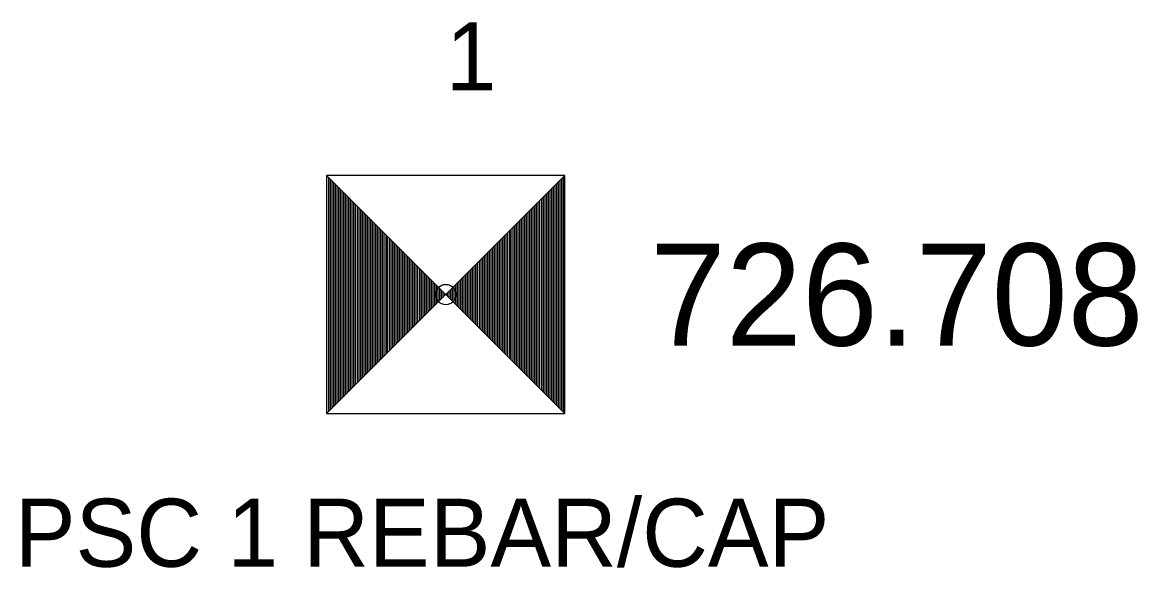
# Model space of a CAD drawing. Extents: x 1655137 to 1657928, y 1003994 to 1005407.
# Drawn here: x 1655137.06 to 1655153.44, y 1005026.6 to 1005034.62 of the extents above; entities that cross this region are included whole.
import ezdxf

# ---------------------------------------------------------------- set-up
doc = ezdxf.new("R2010")
doc.units = 0
for name, color, linetype in [('RD_HC_Survey', 7, 'Continuous'), ('RD_HC_Survey_ELEV', 7, 'Continuous'), ('RD_HC_txCode', 7, 'Continuous'), ('RD_SMD_Locator', 7, 'Continuous')]:
    doc.layers.add(name, color=color, linetype=linetype)

msp = doc.modelspace()

# ---------------------------------------------------------------- linework, layer by layer
at = {"layer": 'RD_HC_Survey'}
for p, q in [((1655141.53, 1005032.367), (1655145.03, 1005028.867)), ((1655145.03, 1005032.367), (1655141.53, 1005028.867)), ((1655141.555, 1005032.343), (1655141.555, 1005028.892)), ((1655141.58, 1005032.318), (1655141.58, 1005028.917)), ((1655141.605, 1005032.293), (1655141.605, 1005028.942)), ((1655141.629, 1005032.268), (1655141.629, 1005028.966)), ((1655141.654, 1005032.244), (1655141.654, 1005028.991)), ((1655141.679, 1005032.219), (1655141.679, 1005029.016)), ((1655141.704, 1005032.194), (1655141.704, 1005029.041)), ((1655144.857, 1005032.194), (1655144.857, 1005029.041)), ((1655144.882, 1005032.219), (1655144.882, 1005029.016)), ((1655144.907, 1005032.244), (1655144.907, 1005028.991)), ((1655144.931, 1005032.268), (1655144.931, 1005028.966)), ((1655144.956, 1005032.293), (1655144.956, 1005028.942)), ((1655144.981, 1005032.318), (1655144.981, 1005028.917)), ((1655145.006, 1005032.343), (1655145.006, 1005028.892)), ((1655141.728, 1005032.169), (1655141.728, 1005029.065)), ((1655141.753, 1005032.145), (1655141.753, 1005029.09)), ((1655141.778, 1005032.12), (1655141.778, 1005029.115)), ((1655141.803, 1005032.095), (1655141.803, 1005029.14)), ((1655141.827, 1005032.07), (1655141.827, 1005029.164)), ((1655141.852, 1005032.046), (1655141.852, 1005029.189)), ((1655144.709, 1005032.046), (1655144.709, 1005029.189)), ((1655144.733, 1005032.07), (1655144.733, 1005029.164)), ((1655144.758, 1005032.095), (1655144.758, 1005029.14)), ((1655144.783, 1005032.12), (1655144.783, 1005029.115)), ((1655144.808, 1005032.145), (1655144.808, 1005029.09)), ((1655144.832, 1005032.169), (1655144.832, 1005029.065)), ((1655141.877, 1005032.021), (1655141.877, 1005029.214)), ((1655141.902, 1005031.996), (1655141.902, 1005029.239)), ((1655141.926, 1005031.971), (1655141.926, 1005029.263)), ((1655141.951, 1005031.947), (1655141.951, 1005029.288)), ((1655141.976, 1005031.922), (1655141.976, 1005029.313)), ((1655142.001, 1005031.897), (1655142.001, 1005029.338)), ((1655142.025, 1005031.872), (1655142.025, 1005029.362)), ((1655144.535, 1005031.872), (1655144.535, 1005029.362)), ((1655144.56, 1005031.897), (1655144.56, 1005029.338)), ((1655144.585, 1005031.922), (1655144.585, 1005029.313)), ((1655144.61, 1005031.947), (1655144.61, 1005029.288)), ((1655144.634, 1005031.971), (1655144.634, 1005029.263)), ((1655144.659, 1005031.996), (1655144.659, 1005029.239)), ((1655144.684, 1005032.021), (1655144.684, 1005029.214)), ((1655142.05, 1005031.848), (1655142.05, 1005029.387)), ((1655142.075, 1005031.823), (1655142.075, 1005029.412)), ((1655142.1, 1005031.798), (1655142.1, 1005029.437)), ((1655142.124, 1005031.773), (1655142.124, 1005029.461)), ((1655142.149, 1005031.749), (1655142.149, 1005029.486)), ((1655142.174, 1005031.724), (1655142.174, 1005029.511)), ((1655144.387, 1005031.724), (1655144.387, 1005029.511)), ((1655144.412, 1005031.749), (1655144.412, 1005029.486)), ((1655144.436, 1005031.773), (1655144.436, 1005029.461)), ((1655144.461, 1005031.798), (1655144.461, 1005029.437)), ((1655144.486, 1005031.823), (1655144.486, 1005029.412)), ((1655144.511, 1005031.848), (1655144.511, 1005029.387)), ((1655142.199, 1005031.699), (1655142.199, 1005029.536)), ((1655142.223, 1005031.674), (1655142.223, 1005029.56)), ((1655142.248, 1005031.65), (1655142.248, 1005029.585)), ((1655142.273, 1005031.625), (1655142.273, 1005029.61)), ((1655142.298, 1005031.6), (1655142.298, 1005029.635)), ((1655142.322, 1005031.575), (1655142.322, 1005029.659)), ((1655142.347, 1005031.551), (1655142.347, 1005029.684)), ((1655144.214, 1005031.551), (1655144.214, 1005029.684)), ((1655144.238, 1005031.575), (1655144.238, 1005029.659)), ((1655144.263, 1005031.6), (1655144.263, 1005029.635)), ((1655144.288, 1005031.625), (1655144.288, 1005029.61)), ((1655144.313, 1005031.65), (1655144.313, 1005029.585)), ((1655144.337, 1005031.674), (1655144.337, 1005029.56)), ((1655144.362, 1005031.699), (1655144.362, 1005029.536)), ((1655142.372, 1005031.526), (1655142.372, 1005029.709)), ((1655142.397, 1005031.501), (1655142.397, 1005029.734)), ((1655142.421, 1005031.476), (1655142.421, 1005029.758)), ((1655142.446, 1005031.452), (1655142.446, 1005029.783)), ((1655142.471, 1005031.427), (1655142.471, 1005029.808)), ((1655142.496, 1005031.402), (1655142.496, 1005029.833)), ((1655142.52, 1005031.377), (1655142.52, 1005029.857)), ((1655144.04, 1005031.377), (1655144.04, 1005029.857)), ((1655144.065, 1005031.402), (1655144.065, 1005029.833)), ((1655144.09, 1005031.427), (1655144.09, 1005029.808)), ((1655144.115, 1005031.452), (1655144.115, 1005029.783)), ((1655144.139, 1005031.476), (1655144.139, 1005029.758)), ((1655144.164, 1005031.501), (1655144.164, 1005029.734)), ((1655144.189, 1005031.526), (1655144.189, 1005029.709)), ((1655142.545, 1005031.353), (1655142.545, 1005029.882)), ((1655142.57, 1005031.328), (1655142.57, 1005029.907)), ((1655142.595, 1005031.303), (1655142.595, 1005029.932)), ((1655142.619, 1005031.278), (1655142.619, 1005029.956)), ((1655142.644, 1005031.254), (1655142.644, 1005029.981)), ((1655142.669, 1005031.229), (1655142.669, 1005030.006)), ((1655143.892, 1005031.229), (1655143.892, 1005030.006)), ((1655143.917, 1005031.254), (1655143.917, 1005029.981)), ((1655143.941, 1005031.278), (1655143.941, 1005029.956)), ((1655143.966, 1005031.303), (1655143.966, 1005029.932)), ((1655143.991, 1005031.328), (1655143.991, 1005029.907)), ((1655144.016, 1005031.353), (1655144.016, 1005029.882)), ((1655142.694, 1005031.204), (1655142.694, 1005030.031)), ((1655142.718, 1005031.179), (1655142.718, 1005030.055)), ((1655142.743, 1005031.155), (1655142.743, 1005030.08)), ((1655142.768, 1005031.13), (1655142.768, 1005030.105)), ((1655142.793, 1005031.105), (1655142.793, 1005030.13)), ((1655142.817, 1005031.08), (1655142.817, 1005030.154)), ((1655142.842, 1005031.056), (1655142.842, 1005030.179)), ((1655143.719, 1005031.056), (1655143.719, 1005030.179)), ((1655143.743, 1005031.08), (1655143.743, 1005030.154)), ((1655143.768, 1005031.105), (1655143.768, 1005030.13)), ((1655143.793, 1005031.13), (1655143.793, 1005030.105)), ((1655143.818, 1005031.155), (1655143.818, 1005030.08)), ((1655143.842, 1005031.179), (1655143.842, 1005030.055)), ((1655143.867, 1005031.204), (1655143.867, 1005030.031)), ((1655142.867, 1005031.031), (1655142.867, 1005030.204)), ((1655142.892, 1005031.006), (1655142.892, 1005030.229)), ((1655142.916, 1005030.981), (1655142.916, 1005030.253)), ((1655142.941, 1005030.957), (1655142.941, 1005030.278)), ((1655142.966, 1005030.932), (1655142.966, 1005030.303)), ((1655142.991, 1005030.907), (1655142.991, 1005030.328)), ((1655143.015, 1005030.882), (1655143.015, 1005030.352)), ((1655143.545, 1005030.882), (1655143.545, 1005030.352)), ((1655143.57, 1005030.907), (1655143.57, 1005030.328)), ((1655143.595, 1005030.932), (1655143.595, 1005030.303)), ((1655143.62, 1005030.957), (1655143.62, 1005030.278)), ((1655143.644, 1005030.981), (1655143.644, 1005030.253)), ((1655143.669, 1005031.006), (1655143.669, 1005030.229)), ((1655143.694, 1005031.031), (1655143.694, 1005030.204)), ((1655143.04, 1005030.858), (1655143.04, 1005030.377)), ((1655143.065, 1005030.833), (1655143.065, 1005030.402)), ((1655143.09, 1005030.808), (1655143.09, 1005030.427)), ((1655143.114, 1005030.783), (1655143.114, 1005030.451)), ((1655143.139, 1005030.759), (1655143.139, 1005030.476)), ((1655143.164, 1005030.734), (1655143.164, 1005030.501)), ((1655143.397, 1005030.734), (1655143.397, 1005030.501)), ((1655143.422, 1005030.759), (1655143.422, 1005030.476)), ((1655143.446, 1005030.783), (1655143.446, 1005030.451)), ((1655143.471, 1005030.808), (1655143.471, 1005030.427)), ((1655143.496, 1005030.833), (1655143.496, 1005030.402)), ((1655143.521, 1005030.858), (1655143.521, 1005030.377)), ((1655143.189, 1005030.709), (1655143.189, 1005030.526)), ((1655143.213, 1005030.684), (1655143.213, 1005030.55)), ((1655143.238, 1005030.66), (1655143.238, 1005030.575)), ((1655143.263, 1005030.635), (1655143.263, 1005030.6)), ((1655143.298, 1005030.635), (1655143.298, 1005030.6)), ((1655143.323, 1005030.66), (1655143.323, 1005030.575)), ((1655143.347, 1005030.684), (1655143.347, 1005030.55)), ((1655143.372, 1005030.709), (1655143.372, 1005030.526))]:
    msp.add_line(p, q, dxfattribs=at)
msp.add_lwpolyline([(1655145.03, 1005032.367), (1655141.53, 1005032.367), (1655141.53, 1005028.867), (1655145.03, 1005028.867)], close=True, dxfattribs=at)
at = {"layer": 'RD_SMD_Locator'}
msp.add_circle((1655143.28, 1005030.617), 0.15, dxfattribs=at)

# ---------------------------------------------------------------- texts
at = {"layer": 'RD_HC_Survey_ELEV'}
msp.add_text('726.708', height=1.5, dxfattribs=at).set_placement((1655146.28, 1005029.867))
at = {"layer": 'RD_HC_txCode'}
for s, p in [('1', (1655143.28, 1005033.617)), ('PSC 1 REBAR/CAP', (1655136.95, 1005026.617))]:
    msp.add_text(s, height=1, dxfattribs=at).set_placement(p)

doc.saveas('drawing.dxf')
